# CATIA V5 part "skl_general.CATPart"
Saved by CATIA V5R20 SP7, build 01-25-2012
Part number: skl_general
Publications: "Longueur_AB", "PlanRef", "PointA", "PointD", "PointC", "PointB", "PointE", "PointG", "PointF", "PointM"
Bounding box of the stored display mesh (mm): x 0 to 0, y -214 to 365.434, z -31.191 to 323.037
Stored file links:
  U:\Projet IAO\omeyer\Catia\skl_general.CATPart
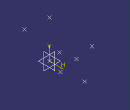
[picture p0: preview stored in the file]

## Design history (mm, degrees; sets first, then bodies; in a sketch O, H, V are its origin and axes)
Parameters
  Longueur_AB = 100 mm
Set1
  Plane1 "PlanRef": type Offset, RefPlane yz-plane, Offset 0
  Point1 "PointA": type OnPlane, Support Plane1, H 0, V 0, Direction (0, 1, 0)
  Point2 "PointD": type OnPlane, Support Plane1, H 300 {= Longueur_AB *3}, V 0, Direction (0, 1, 0)
  Circle1: type CtrRad, Start 0, End 180, Center Point2, Support Plane1, Radius 530 {= Longueur_AB *5.3}, FirstDirection (0, 1, 0)
  Circle2: type CtrRad, Start 0, End 180, Center Point1, Support Plane1, Radius 250 {= Longueur_AB *2.5}, FirstDirection (0, 1, 0)
  Circle3: type CtrRad, Start 0, End 180, Center Point1, Support Plane1, Radius 100 {= Longueur_AB}, FirstDirection (0, 1, 0)
  Circle4: type CtrRad, Start 0, End 180, Center Point2, Support Plane1, Radius 300 {= Longueur_AB *3}, FirstDirection (0, 1, 0)
  Point3 "PointB": type OnCurve, Support Circle3, RefPoint {extremum Reference Circle3, Direction (1, 2, 3)}, Length 130 {= Longueur_AB *1.3}
  Circle5: type CtrRad, Start 0, End 180, Center Point3, Support Plane1, Radius 422 {= Longueur_AB *4.22}, FirstDirection (0, 1, 0)
  Intersect1 "PointC": ToIntersect1 Circle4, ToIntersect2 Circle5
  Point4 "PointM": type Between, FirstPoint Point3, SecondPoint Intersect1, Ratio 0.5
  Line1: type PtPt, FirstPoint Intersect1, SecondPoint Point3
  Line2: type Angle, RefPoint Point4, Curve Line1, Support Plane1, Start 0, End 600 {= Longueur_AB *6}, Angle 90
  Circle6: type CtrRad, Start 0, End 180, Center Point4, Support Plane1, Radius 300 {= Longueur_AB *3}, FirstDirection (0, 1, 0)
  Intersect2 "PointE": ToIntersect1 Circle6, ToIntersect2 Line2
  Intersect3 "PointG": ToIntersect1 Circle2, ToIntersect2 Circle1
  Circle7: type CtrRad, Start -200, End 20, Center Intersect3, Support Plane1, Radius 300 {= Longueur_AB *3}, FirstDirection (0, 1, 0)
  Circle8: type CtrRad, Start 0, End 180, Center Intersect2, Support Plane1, Radius 233 {= Longueur_AB *2.33}, FirstDirection (0, 1, 0)
  Intersect4 "PointF": ToIntersect1 Circle8, ToIntersect2 Circle7
Body1 (main body)
  Sketch1 on Plane1, origin (0, 0, 0), H (0, 1, 0), V (0, 0, 1)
